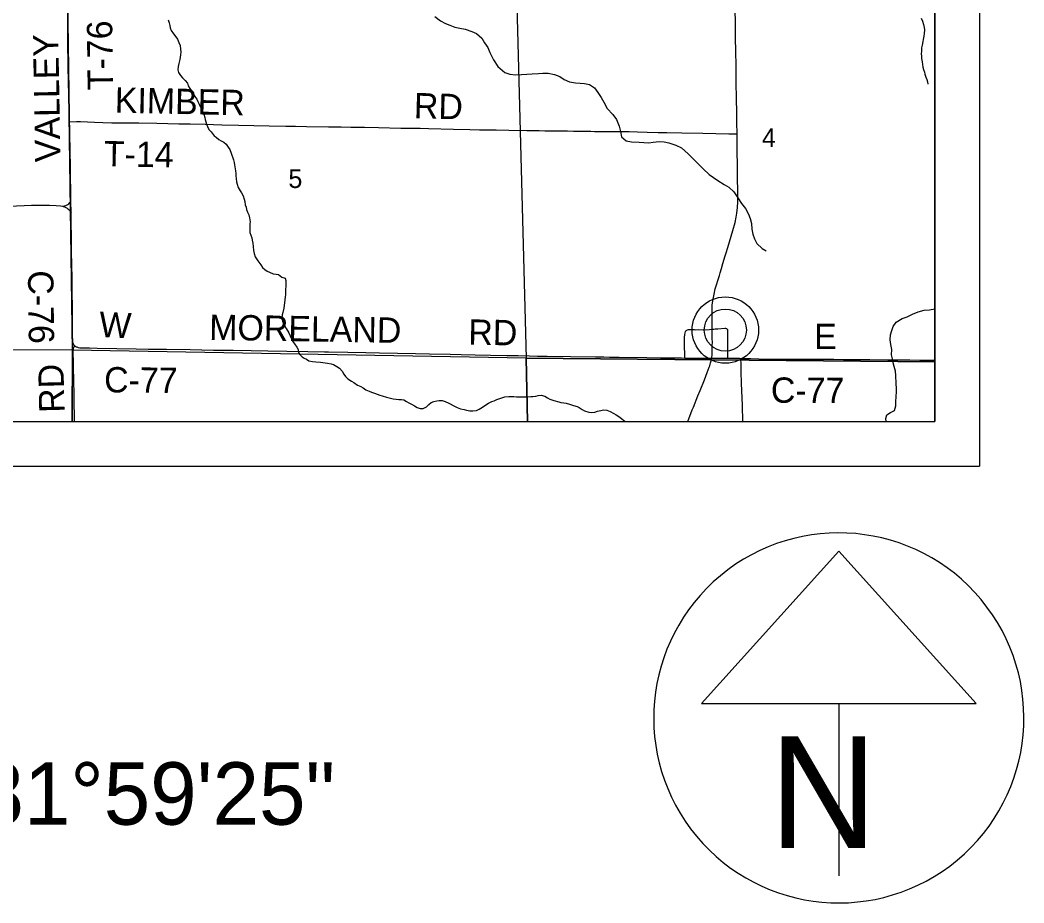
# Model space of a CAD drawing. Extents: x 0 to 34, y 0 to 22.
# Drawn here: x 6.85 to 9.099, y 13.02 to 15 of the extents above; entities that cross this region are included whole.
import ezdxf

# ---------------------------------------------------------------- set-up
doc = ezdxf.new("R2010")
doc.units = 0
for name, color, linetype in [('GM_X_County_Road', 7, 'Continuous'), ('GM_X_County_Road_Text', 7, 'Continuous'), ('GM_X_Minor_River', 7, 'Continuous'), ('GM_X_Section', 7, 'Continuous'), ('GM_X_Section_Text', 7, 'Continuous'), ('GM_X_State_Route', 7, 'Continuous'), ('GM_X_Township_Road', 7, 'Continuous'), ('GM_X_Township_Road_Text', 7, 'Continuous'), ('GM_X_Unincorporated', 7, 'Continuous'), ('GM_X_Unincorporated_Location', 7, 'Continuous'), ('SH_Data', 7, 'Continuous'), ('SH_Text', 7, 'Continuous')]:
    doc.layers.add(name, color=color, linetype=linetype)

msp = doc.modelspace()

# ---------------------------------------------------------------- linework, layer by layer
at = {"layer": 'GM_X_County_Road'}
for points in [[(6.8253, 14.5828), (6.8749, 14.5846), (6.8966, 14.5849), (6.9153, 14.5846), (6.9308, 14.584), (6.9402, 14.583), (6.9445, 14.5824), (6.946, 14.5821)], [(6.946, 14.5821), (6.9487, 14.583), (6.9519, 14.584), (6.9536, 14.5847), (6.955, 14.5855), (6.9568, 14.5865), (6.9587, 14.5879), (6.9614, 14.5908), (6.9624, 14.5923), (6.9637, 14.5944)], [(6.946, 14.5821), (6.9468, 14.5819), (6.9483, 14.5815), (6.9494, 14.581), (6.9524, 14.5798), (6.9552, 14.5781), (6.9577, 14.5761), (6.9597, 14.5742), (6.9619, 14.571), (6.9639, 14.5676)], [(6.9725, 14.2694), (6.9716, 14.2701), (6.9709, 14.2709), (6.9704, 14.2715), (6.9697, 14.2726), (6.969, 14.2738), (6.9684, 14.2752), (6.9678, 14.2768), (6.9675, 14.2784), (6.967, 14.2812), (6.9667, 14.2872), (6.9668, 14.2965), (6.967, 14.343), (6.9668, 14.3617), (6.9667, 14.3835), (6.9661, 14.4177), (6.9654, 14.455), (6.965, 14.4767), (6.9646, 14.5046), (6.9642, 14.5543), (6.9641, 14.5603), (6.9639, 14.5676)], [(6.9716, 14.1), (6.9715, 14.1133), (6.9709, 14.1393), (6.9707, 14.1671), (6.9702, 14.1847), (6.97, 14.1984), (6.9697, 14.2139), (6.9693, 14.2355), (6.9689, 14.2507), (6.9689, 14.2545), (6.9689, 14.2594), (6.9692, 14.262), (6.9697, 14.2642), (6.9701, 14.2657), (6.9707, 14.2671), (6.9714, 14.2681), (6.9725, 14.2694)], [(6.9725, 14.2694), (6.974, 14.2683), (6.9752, 14.2675), (6.9767, 14.2669), (6.9795, 14.266), (6.9837, 14.2651), (6.9898, 14.2648), (6.9947, 14.2648), (7.0049, 14.2648), (7.0227, 14.2644), (7.0662, 14.2636), (7.1097, 14.2628), (7.1376, 14.2623), (7.1779, 14.2617), (7.2307, 14.2609), (7.2834, 14.2601), (7.3269, 14.2596), (7.3672, 14.2589), (7.4045, 14.2584), (7.4477, 14.2578), (7.4942, 14.2569), (7.5315, 14.2563), (7.5408, 14.2562), (7.5842, 14.2551), (7.6244, 14.2543), (7.6554, 14.2536), (7.6958, 14.2531), (7.7361, 14.252), (7.7671, 14.2513), (7.8137, 14.2505), (7.8385, 14.25), (7.8695, 14.2494), (7.9036, 14.2486), (7.9408, 14.248), (7.9656, 14.2476), (7.9915, 14.2468), (8.0091, 14.2466), (8.0307, 14.2461), (8.0835, 14.2454), (8.1394, 14.2449), (8.158, 14.2446), (8.1704, 14.2444), (8.1921, 14.244), (8.2542, 14.2433), (8.2852, 14.2428), (8.3007, 14.2426), (8.3316, 14.2422), (8.3396, 14.2421)], [(8.3396, 14.2421), (8.3625, 14.2419), (8.3808, 14.2419), (8.3948, 14.242), (8.3996, 14.242)], [(8.3996, 14.242), (8.4071, 14.2419), (8.4261, 14.2418), (8.4349, 14.2417)], [(8.4349, 14.2417), (8.4622, 14.2415), (8.4649, 14.2414)], [(8.4649, 14.2414), (8.487, 14.2407), (8.5056, 14.2402), (8.5304, 14.2398), (8.5894, 14.2395), (8.6733, 14.2392), (8.695, 14.2391), (8.7539, 14.2386), (8.7943, 14.2383), (8.8222, 14.238), (8.844, 14.2378), (8.8657, 14.2376), (8.9, 14.2374)]]:
    msp.add_lwpolyline(points, dxfattribs=at)
at = {"layer": 'GM_X_Minor_River'}
for points in [[(7.7794, 15.0076), (7.7919, 14.9982), (7.8033, 14.9922), (7.8128, 14.9884), (7.8242, 14.9836), (7.8352, 14.9813), (7.8473, 14.9791), (7.862, 14.9743), (7.8727, 14.9698), (7.8848, 14.9592), (7.8905, 14.949), (7.8978, 14.938), (7.9024, 14.927), (7.9108, 14.9103), (7.9203, 14.896), (7.9359, 14.882), (7.9469, 14.8786), (7.9597, 14.8772), (7.9734, 14.878), (7.9851, 14.8784), (7.9972, 14.8796), (8.0112, 14.8801), (8.0214, 14.8809), (8.0331, 14.8809), (8.0471, 14.8776), (8.0589, 14.8731), (8.0691, 14.8663), (8.0812, 14.8614), (8.0945, 14.8592), (8.1047, 14.8585)], [(7.1814, 15.0001), (7.1836, 14.9933), (7.1855, 14.9879), (7.1863, 14.9822), (7.1886, 14.9761), (7.1931, 14.9693), (7.1984, 14.9624), (7.2022, 14.9567), (7.2057, 14.9495), (7.2083, 14.9427), (7.2095, 14.9343), (7.2099, 14.9282), (7.2091, 14.9218), (7.2084, 14.9165), (7.2076, 14.9115), (7.2057, 14.9024), (7.2038, 14.8956), (7.2031, 14.888), (7.2046, 14.8823), (7.2088, 14.8758), (7.2137, 14.8705), (7.2194, 14.864), (7.2251, 14.8587), (7.2266, 14.8526), (7.23, 14.8461), (7.2335, 14.8408), (7.238, 14.8332), (7.2414, 14.8282), (7.2456, 14.8221), (7.2483, 14.8172), (7.2509, 14.8115), (7.2543, 14.8043), (7.2566, 14.7993), (7.2593, 14.7936), (7.2616, 14.7887), (7.2638, 14.7815), (7.2646, 14.7765), (7.2657, 14.7716), (7.2673, 14.7666), (7.2695, 14.7613), (7.273, 14.7545), (7.2775, 14.7491), (7.2843, 14.7404), (7.2893, 14.7369), (7.2953, 14.7324), (7.3006, 14.7293), (7.3063, 14.7259), (7.3113, 14.7217), (7.3158, 14.7152), (7.3196, 14.7099)], [(8.869, 15.0042), (8.8717, 14.9977), (8.874, 14.9901), (8.8759, 14.9829), (8.8763, 14.978), (8.8759, 14.9696), (8.8748, 14.9635), (8.8733, 14.9563), (8.8725, 14.9514), (8.8714, 14.9438), (8.8699, 14.9373), (8.8695, 14.9297), (8.8692, 14.924), (8.8695, 14.9191), (8.8699, 14.9137), (8.8711, 14.9061), (8.8722, 14.9001), (8.873, 14.8944), (8.8745, 14.889), (8.8764, 14.8833), (8.8776, 14.8784), (8.8795, 14.8719), (8.8814, 14.8662), (8.8829, 14.8613), (8.884, 14.856)], [(8.1047, 14.8585), (8.1149, 14.8574), (8.1255, 14.8552), (8.1369, 14.848), (8.1445, 14.8374), (8.1518, 14.8261), (8.1579, 14.8155), (8.1655, 14.8019), (8.1784, 14.7883), (8.1864, 14.7769), (8.1922, 14.7618), (8.1949, 14.7496), (8.1976, 14.7379), (8.2079, 14.7288), (8.22, 14.7266), (8.2374, 14.7263), (8.2476, 14.7256), (8.2589, 14.7249), (8.2688, 14.7261), (8.282, 14.7273), (8.293, 14.7266), (8.3036, 14.7243), (8.3191, 14.7195), (8.332, 14.7135), (8.3468, 14.7002), (8.3571, 14.6897), (8.3677, 14.6787), (8.3807, 14.6662), (8.394, 14.6538), (8.4038, 14.6466), (8.4137, 14.6402), (8.4274, 14.6315), (8.438, 14.6255), (8.4494, 14.6146), (8.4585, 14.6013), (8.4662, 14.5888), (8.4753, 14.5771), (8.4822, 14.565), (8.4856, 14.5552), (8.4887, 14.5438), (8.4899, 14.5313), (8.4918, 14.5199), (8.4953, 14.5093), (8.501, 14.4991), (8.5124, 14.4873), (8.5219, 14.4821)], [(7.3196, 14.7099), (7.323, 14.7016), (7.328, 14.6867), (7.3295, 14.6806), (7.3303, 14.6753), (7.3318, 14.6666), (7.3322, 14.6616), (7.3329, 14.6559), (7.3333, 14.6506), (7.3341, 14.6445), (7.3349, 14.6369), (7.336, 14.6316), (7.3383, 14.6244), (7.3428, 14.6172), (7.3459, 14.6122), (7.3497, 14.6057), (7.352, 14.5985), (7.3535, 14.5932), (7.3542, 14.5856), (7.3561, 14.5803), (7.3573, 14.5749), (7.3596, 14.5692), (7.3622, 14.5628), (7.3641, 14.5563), (7.3653, 14.5476), (7.3649, 14.5426), (7.3645, 14.5369), (7.3642, 14.532), (7.3642, 14.5236), (7.3668, 14.5179), (7.3691, 14.5115), (7.3699, 14.5061), (7.371, 14.4993), (7.3722, 14.4921), (7.3726, 14.4833), (7.3745, 14.4761), (7.3768, 14.4693), (7.3828, 14.4598), (7.3889, 14.4514), (7.3927, 14.4449), (7.398, 14.4407), (7.4037, 14.4369), (7.4086, 14.4343), (7.4166, 14.4312), (7.4234, 14.4301), (7.4287, 14.4293), (7.4366, 14.4236), (7.4435, 14.4213), (7.445, 14.416), (7.4454, 14.411), (7.445, 14.4023), (7.4446, 14.3962), (7.4446, 14.3901), (7.4443, 14.384), (7.4435, 14.3791), (7.4432, 14.3726), (7.4424, 14.3658), (7.4417, 14.3609), (7.4405, 14.3536), (7.4383, 14.3441), (7.4368, 14.3392), (7.436, 14.3308), (7.4379, 14.3244), (7.4402, 14.3187), (7.4429, 14.3134), (7.4463, 14.3084), (7.4516, 14.2989), (7.455, 14.2921), (7.4603, 14.2799), (7.4649, 14.2738), (7.4698, 14.2666), (7.4725, 14.2612), (7.4736, 14.2552), (7.4767, 14.2498), (7.4816, 14.2445), (7.4865, 14.2415), (7.4914, 14.2392), (7.4971, 14.2361), (7.5047, 14.2342), (7.5127, 14.2334), (7.5229, 14.2327), (7.5278, 14.2319), (7.5331, 14.2311), (7.5388, 14.2304), (7.5471, 14.2288), (7.552, 14.2273), (7.5596, 14.2231), (7.5653, 14.2193), (7.5714, 14.2124), (7.5755, 14.206), (7.579, 14.201), (7.5843, 14.1957), (7.5926, 14.19), (7.5975, 14.1869), (7.6059, 14.1816), (7.6131, 14.1782), (7.6184, 14.1751), (7.6248, 14.1706), (7.632, 14.1675), (7.6373, 14.1652), (7.6441, 14.1637)], [(8.7904, 14.1), (8.7901, 14.1067), (8.7919, 14.1151), (8.8003, 14.12), (8.809, 14.1245), (8.812, 14.1348), (8.812, 14.1435), (8.8127, 14.1564), (8.8138, 14.1652), (8.8134, 14.1735), (8.8127, 14.1849), (8.8126, 14.2032), (8.8115, 14.2127), (8.8088, 14.2233), (8.8065, 14.2317), (8.8046, 14.2401), (8.8027, 14.2496), (8.8031, 14.261), (8.8008, 14.2728), (8.7997, 14.283), (8.8, 14.2944), (8.803, 14.3035), (8.806, 14.3126), (8.8132, 14.3225), (8.8261, 14.3305), (8.8374, 14.3346), (8.8499, 14.3407), (8.862, 14.346), (8.8757, 14.3494), (8.8878, 14.3505), (8.9, 14.3526)], [(7.6441, 14.1637), (7.6498, 14.161), (7.6555, 14.1587), (7.6612, 14.1572), (7.671, 14.1545), (7.6771, 14.1526), (7.6858, 14.1503), (7.6923, 14.1499), (7.6983, 14.1492), (7.7048, 14.1488), (7.7097, 14.1484), (7.7157, 14.1449), (7.7207, 14.1419), (7.7271, 14.1388), (7.7336, 14.1347), (7.7392, 14.1312), (7.7461, 14.1289), (7.7533, 14.1293), (7.7604, 14.1327), (7.7657, 14.138), (7.771, 14.1422), (7.7767, 14.1448), (7.7835, 14.1464), (7.7892, 14.1467), (7.7953, 14.1467), (7.8021, 14.1448), (7.8108, 14.1406), (7.8229, 14.1345), (7.829, 14.1311), (7.8369, 14.1284), (7.8445, 14.1265), (7.8502, 14.125), (7.8574, 14.1234), (7.8646, 14.1238), (7.8722, 14.1245), (7.8782, 14.1272), (7.8862, 14.1321), (7.8937, 14.1374), (7.8994, 14.1408), (7.907, 14.1443), (7.9119, 14.1461), (7.9179, 14.1492), (7.927, 14.1522), (7.9361, 14.1548), (7.9448, 14.156), (7.9501, 14.156), (7.9562, 14.1556), (7.9619, 14.1552), (7.9668, 14.1548), (7.9762, 14.1552), (7.9876, 14.1551), (7.994, 14.1555), (7.999, 14.1555), (8.0058, 14.1563), (8.0107, 14.1578), (8.0175, 14.1589), (8.0255, 14.1566), (8.0319, 14.1532), (8.0372, 14.1501), (8.0455, 14.1471), (8.0569, 14.144), (8.0618, 14.1425), (8.0683, 14.1417), (8.0732, 14.1406), (8.0808, 14.1386), (8.0899, 14.136), (8.0978, 14.1337), (8.1027, 14.131), (8.1092, 14.1264), (8.1145, 14.1234), (8.1243, 14.1207), (8.1312, 14.1203), (8.1376, 14.1211), (8.144, 14.123), (8.1508, 14.1248), (8.1569, 14.1256), (8.1645, 14.1252), (8.1721, 14.1222), (8.1804, 14.118), (8.1857, 14.1149), (8.1914, 14.1111), (8.1971, 14.1069), (8.2028, 14.1023), (8.2065, 14.1)]]:
    msp.add_lwpolyline(points, dxfattribs=at)
at = {"layer": 'GM_X_Section'}
for points in [[(6.9531, 15.2604), (6.9669, 14.2596), (5.7673, 14.2653), (5.7637, 15.2651), (6.9228, 15.2602)], [(6.9531, 15.2604), (7.9294, 15.2601), (7.9571, 15.2595), (7.9839, 14.2421), (6.9669, 14.2596)]]:
    msp.add_lwpolyline(points, close=True, dxfattribs=at)
at = {"layer": 'GM_X_State_Route'}
for points in [[(8.456, 14.7703), (8.4559, 14.7753), (8.4556, 14.8002), (8.4552, 14.8157), (8.4552, 14.825), (8.4547, 14.8592), (8.4545, 14.8809), (8.4542, 14.9058), (8.4538, 14.9213), (8.4532, 14.9679), (8.4526, 14.9989), (8.4524, 15.0176), (8.4519, 15.0424), (8.4516, 15.0672), (8.4519, 15.0796), (8.4524, 15.0857)], [(8.3458, 14.1), (8.356, 14.1256), (8.3585, 14.1321), (8.3687, 14.1571), (8.3735, 14.1694), (8.3832, 14.1929), (8.3897, 14.2093), (8.3942, 14.2214), (8.3952, 14.2247), (8.3965, 14.2287), (8.3972, 14.2316), (8.3988, 14.2378), (8.3996, 14.242), (8.4004, 14.2505), (8.4008, 14.2598), (8.4008, 14.266), (8.4009, 14.2721), (8.4012, 14.2752), (8.401, 14.2874), (8.4008, 14.2905), (8.4008, 14.2966), (8.4007, 14.3002), (8.4007, 14.3068), (8.4005, 14.3214), (8.4004, 14.3275), (8.4005, 14.333), (8.4005, 14.3362), (8.4004, 14.3517), (8.4006, 14.3609), (8.4018, 14.37), (8.4048, 14.3851), (8.4076, 14.3971), (8.4101, 14.4059), (8.4138, 14.4181), (8.4168, 14.4275), (8.4185, 14.4332), (8.4214, 14.4425), (8.4249, 14.4541), (8.4299, 14.4711), (8.4319, 14.4779), (8.4357, 14.4897), (8.447, 14.5279), (8.4519, 14.5458), (8.4546, 14.5579), (8.4561, 14.5671), (8.4574, 14.5795), (8.4582, 14.592), (8.4584, 14.6013), (8.4567, 14.7194), (8.4565, 14.7349), (8.4564, 14.7449), (8.456, 14.7703)]]:
    msp.add_lwpolyline(points, dxfattribs=at)
at = {"layer": 'GM_X_Township_Road'}
msp.add_line((6.9639, 14.5676), (6.9637, 14.5944), dxfattribs=at)
msp.add_lwpolyline([(5.7705, 14.1), (8.9, 14.1), (8.9, 17.2634), (8.4218, 17.2637), (7.9163, 17.252), (7.9297, 16.3619), (7.9298, 16.2686), (7.9298, 16.2367), (7.9301, 16.1134), (7.9306, 15.7658), (7.9283, 15.2595), (6.9226, 15.2644), (5.7675, 15.2711), (5.7694, 14.855)], close=True, dxfattribs=at)
for points in [[(6.9605, 14.7714), (6.9605, 14.7744), (6.9604, 14.7755), (6.9603, 14.7772), (6.9595, 14.7921), (6.9586, 14.8357), (6.9583, 14.8575), (6.958, 14.8696), (6.9577, 14.8877), (6.9575, 14.8979), (6.9574, 14.9073), (6.9569, 14.9402), (6.9567, 14.9648), (6.9568, 14.9928), (6.9564, 15.0366)], [(6.9605, 14.7714), (6.976, 14.7722), (6.9853, 14.7722), (7.0163, 14.771), (7.035, 14.7702), (7.0552, 14.7697), (7.0635, 14.7696), (7.0722, 14.7694), (7.0815, 14.7695), (7.097, 14.7695), (7.1156, 14.7692), (7.156, 14.7685), (7.2056, 14.7673), (7.2305, 14.7668), (7.2647, 14.7663), (7.302, 14.7652), (7.3392, 14.764), (7.4076, 14.7628), (7.4449, 14.7619), (7.4667, 14.7616), (7.4915, 14.7611), (7.5411, 14.7606), (7.5566, 14.7604), (7.569, 14.7603), (7.5907, 14.7599), (7.6063, 14.7596), (7.6218, 14.7594), (7.6529, 14.7588), (7.7026, 14.7576), (7.7118, 14.7577), (7.746, 14.7571), (7.7647, 14.7567), (7.8206, 14.7554), (7.8578, 14.7545), (7.8796, 14.754), (7.9169, 14.7537), (7.9448, 14.7531), (7.9853, 14.7525), (8.0008, 14.7522), (8.007, 14.7522), (8.0132, 14.7521), (8.0257, 14.7518), (8.0381, 14.7516), (8.0566, 14.7515), (8.0764, 14.7511), (8.0896, 14.7509), (8.1003, 14.7507), (8.1063, 14.7506), (8.1192, 14.7505), (8.1284, 14.7504), (8.1373, 14.7503), (8.1496, 14.7501), (8.159, 14.7499), (8.1715, 14.7501), (8.1892, 14.75), (8.2004, 14.7499), (8.2149, 14.7498), (8.2335, 14.7491), (8.2552, 14.7482), (8.28, 14.7476), (8.2987, 14.7474), (8.3328, 14.7469), (8.3794, 14.7461), (8.4382, 14.7451), (8.4505, 14.745), (8.4564, 14.7449)], [(6.9637, 14.5944), (6.9637, 14.5982), (6.9629, 14.6669), (6.9622, 14.7106), (6.9613, 14.7418), (6.961, 14.7574), (6.9605, 14.7714)], [(6.9725, 14.2694), (6.9716, 14.2701), (6.9709, 14.2709), (6.9704, 14.2715), (6.9697, 14.2726), (6.969, 14.2738), (6.9684, 14.2752), (6.9678, 14.2768), (6.9675, 14.2784), (6.967, 14.2812), (6.9667, 14.2872), (6.9668, 14.2965), (6.967, 14.343), (6.9668, 14.3617), (6.9667, 14.3835), (6.9661, 14.4177), (6.9654, 14.455), (6.965, 14.4767), (6.9646, 14.5046), (6.9642, 14.5543), (6.9641, 14.5603), (6.9639, 14.5676)], [(8.4007, 14.3068), (8.4045, 14.307), (8.4072, 14.3073), (8.4099, 14.3075), (8.4134, 14.3078), (8.4291, 14.3087), (8.4305, 14.3088), (8.4318, 14.3086), (8.4331, 14.308), (8.434, 14.3071), (8.4347, 14.3058), (8.4351, 14.3042), (8.435, 14.3005), (8.4349, 14.2831), (8.4348, 14.2617), (8.4349, 14.2466), (8.4349, 14.2417)], [(8.3396, 14.2421), (8.3395, 14.2448), (8.3393, 14.2497), (8.3392, 14.2549), (8.339, 14.2637), (8.339, 14.2666), (8.339, 14.2712), (8.3389, 14.2754), (8.3388, 14.2812), (8.3389, 14.2856), (8.339, 14.2892), (8.3393, 14.2941), (8.34, 14.2988), (8.3409, 14.3017), (8.3417, 14.303), (8.3428, 14.3041), (8.3439, 14.3048), (8.3454, 14.3054), (8.3478, 14.3058), (8.3515, 14.306), (8.3554, 14.3059), (8.3612, 14.3057), (8.3643, 14.3056), (8.3705, 14.3057), (8.386, 14.3056), (8.3946, 14.3061), (8.4007, 14.3068)], [(6.9716, 14.1), (6.9715, 14.1133), (6.9709, 14.1393), (6.9707, 14.1671), (6.9702, 14.1847), (6.97, 14.1984), (6.9697, 14.2139), (6.9693, 14.2355), (6.9689, 14.2507), (6.9689, 14.2545), (6.9689, 14.2594), (6.9692, 14.262), (6.9697, 14.2642), (6.9701, 14.2657), (6.9707, 14.2671), (6.9714, 14.2681), (6.9725, 14.2694)], [(8.4696, 14.1), (8.4685, 14.1357), (8.4665, 14.1857), (8.4658, 14.2108), (8.4654, 14.2276), (8.4649, 14.2414)]]:
    msp.add_lwpolyline(points, dxfattribs=at)
at = {"layer": 'GM_X_Unincorporated'}
for points in [[(8.9, 14.2334), (8.9, 15.2555), (7.9571, 15.2595), (7.9839, 14.2421)], [(5.7666, 14.1), (6.9665, 14.1), (6.9669, 14.2596), (5.7673, 14.2653)], [(6.9665, 14.1), (7.987, 14.1), (7.9839, 14.2421), (6.9669, 14.2596)], [(7.987, 14.1), (8.9, 14.1), (8.9, 14.2334), (7.9839, 14.2421)]]:
    msp.add_lwpolyline(points, close=True, dxfattribs=at)
for radius in [0.0744, 0.0472]:
    msp.add_circle((8.4302, 14.3048), radius, dxfattribs=at)
at = {"layer": 'GM_X_Unincorporated_Location'}
msp.add_line((8.4302, 14.3048), (8.4302, 14.3048), dxfattribs=at)
at = {"layer": 'SH_Data'}
for p, q in [((9, 21), (9, 14)), ((8.9, 20.9), (8.9, 14.1)), ((2.1, 14.1), (8.9, 14.1)), ((2, 14), (9, 14)), ((8.6845, 13.809), (8.3769, 13.4678)), ((8.9921, 13.4678), (8.6845, 13.809)), ((8.3769, 13.4678), (8.9921, 13.4678)), ((8.6845, 13.4678), (8.6845, 13.081)), ((8.6845, 13.4353), (8.6845, 13.4353)), ((8.6845, 13.4353), (8.6845, 13.4353))]:
    msp.add_line(p, q, dxfattribs=at)
msp.add_arc((8.6845, 13.4353), 0.4148, 129.7798, 129.7633, dxfattribs=at)

# ---------------------------------------------------------------- texts
at = {"layer": 'GM_X_County_Road_Text'}
for s, height, rotation, p in [('C-76', 0.05682, 270.6857, (6.8673, 14.4384)), ('W', 0.0568, 357.1976, (7.0257, 14.2895)), ('MORELAND', 0.05682, 359.0526, (7.2731, 14.283)), ('RD', 0.05682, 359.0132, (7.8538, 14.2721)), ('E', 0.0568, 0, (8.6293, 14.2621)), ('C-77', 0.05682, 359.316, (7.0377, 14.1653)), ('C-77', 0.05682, 359.6563, (8.5321, 14.1419))]:
    msp.add_text(s, height=height, rotation=rotation, dxfattribs=at).set_placement(p)
at = {"layer": 'GM_X_Section_Text'}
for s, p in [('4', (8.5122, 14.7152)), ('5', (7.451, 14.6233))]:
    msp.add_text(s, height=0.0419, rotation=0, dxfattribs=at).set_placement(p)
at = {"layer": 'GM_X_Township_Road_Text'}
for s, rotation, p in [('T-76', 90.6983, (7.0579, 14.8429)), ('VALLEY', 91.0251, (6.9403, 14.6817)), ('KIMBER', 358.7699, (7.0614, 14.7923)), ('RD', 358.5112, (7.7316, 14.7798)), ('T-14', 358.9521, (7.037, 14.672)), ('RD', 91.4501, (6.9495, 14.12))]:
    msp.add_text(s, height=0.05682, rotation=rotation, dxfattribs=at).set_placement(p)
at = {"layer": 'SH_Data'}
msp.add_text('N', height=0.25, dxfattribs=at).set_placement((8.5292, 13.1439))
at = {"layer": 'SH_Text'}
msp.add_text('LATITUDE:  N40°45\'33"     LONGITUDE:  W81°59\'25"', height=0.14, dxfattribs=at).set_placement((3.071, 13.1958))

doc.saveas('drawing.dxf')
